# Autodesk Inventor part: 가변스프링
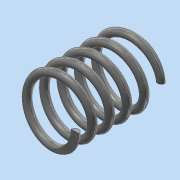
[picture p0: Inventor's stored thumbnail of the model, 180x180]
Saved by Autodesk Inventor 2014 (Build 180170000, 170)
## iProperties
Created: 2026-06
Part Number: 가변스프링
Material: 강철, 합금
Document SubType Name: Modeling
Designer: dg
Density: 7.85 g/cm^3
Appearance: 반연마
Mass: 5.7037 g
Surface Area: 14.7819 cm^2
Volume: 0.726586 cm^3
Author: dg
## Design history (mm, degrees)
sketch "스케치1"
  geometry: L1 (0, 0)-(7.5, 0); L2 (0, 0)-(0, 23); L3 (0, 23)-(5.76, 23); C1 r 1 at (7.5, 0)
  constraints: 6 end point, 2 horizontal, 1 centre point, 1 coincident, 1 perpendicular
  dimensions: "d0" = 15 diameter of L1.end L2; "d1" = 2 diameter of C1; "d2" = 23 distance from line of L3 L1.end (derived)
feature "코일1" sketch "스케치1" pitch "d3" = 10; turns "d5" = 5; dims "d4" = 23 (= d2), "d6" = 0, angle "d7" = 90 deg, angle "d8" = 90 deg, "d9" = 0, "d10" = 0
node "작업 평면1"
feature "분할1"
feature "분할2"
node "솔리드1"
other parameters: "d11" = 0
